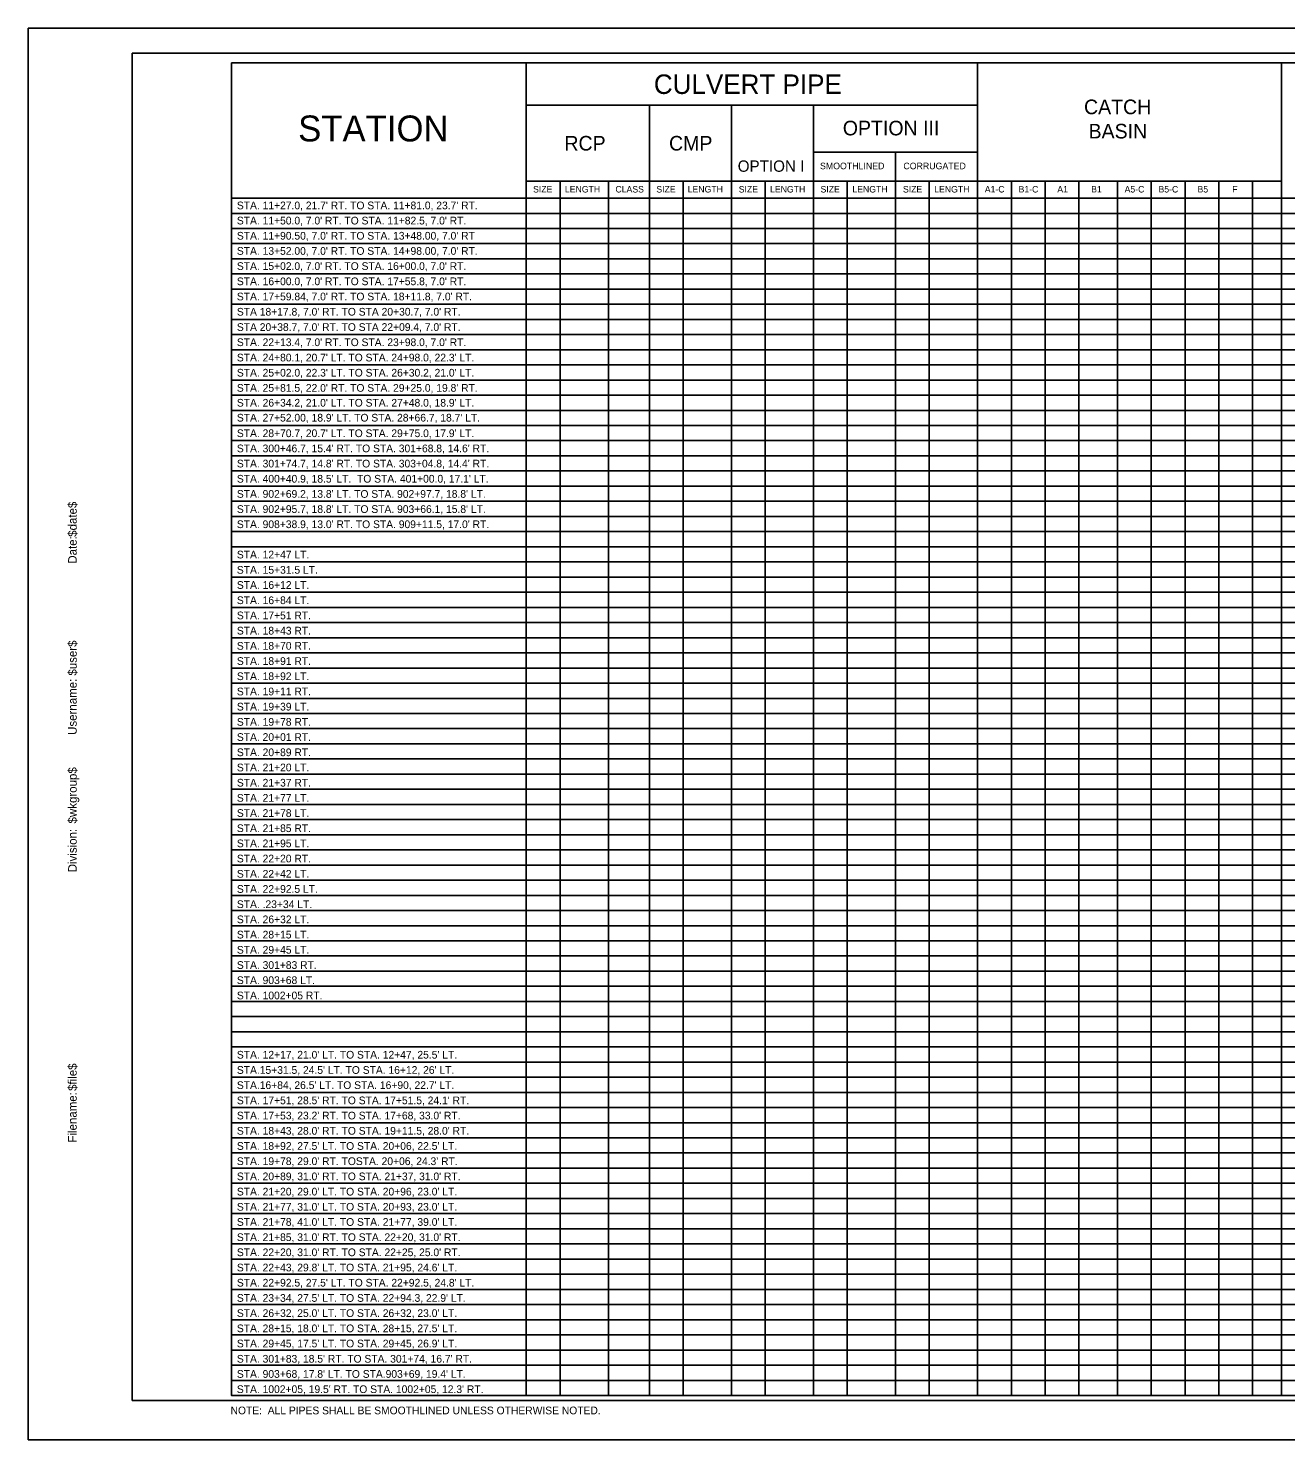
# Model space of a CAD drawing. Extents: x -0.13 to 2.7, y -0.05 to 1.78.
# Drawn here: x -0.135 to 1.498, y -0.051 to 1.782 of the extents above; entities that cross this region are included whole.
import ezdxf

# ---------------------------------------------------------------- set-up
doc = ezdxf.new("R2010")
doc.units = 0
for name, color, linetype in [('ANNOTATION', 7, 'Continuous'), ('BORDER', 7, 'Continuous'), ('PLOT BOUNDARY', 7, 'Continuous')]:
    doc.layers.add(name, color=color, linetype=linetype)

msp = doc.modelspace()

# ---------------------------------------------------------------- linework, layer by layer
at = {"layer": 'BORDER'}
for p, q in [((2.6667, 1.75), (0, 1.75)), ((0, 1.75), (0, 0)), ((0.512, 1.6825), (0.512, 1.7373)), ((1.0982, 1.6825), (1.0982, 1.7373)), ((1.4929, 0.0065), (1.4929, 1.7373)), ((0.512, 1.6214), (0.512, 1.6825)), ((0.512, 1.6825), (0.5559, 1.6825)), ((0.5559, 1.6825), (0.6186, 1.6825)), ((0.6186, 1.6825), (0.6719, 1.6825)), ((0.6719, 1.6214), (0.6719, 1.6825)), ((0.6719, 1.6825), (0.7158, 1.6825)), ((0.7158, 1.6825), (0.7785, 1.6825)), ((0.7785, 1.6214), (0.7785, 1.6825)), ((0.7785, 1.6825), (0.8223, 1.6825)), ((0.8223, 1.6825), (0.9289, 1.6825)), ((0.885, 1.5836), (0.885, 1.6825)), ((0.9289, 1.6825), (1.0982, 1.6825)), ((1.0982, 1.6214), (1.0982, 1.6825)), ((0.512, 1.5836), (0.512, 1.6214)), ((0.6719, 1.5836), (0.6719, 1.6214)), ((0.7785, 1.5836), (0.7785, 1.6214)), ((0.885, 1.6214), (0.9289, 1.6214)), ((0.9289, 1.6214), (1.0354, 1.6214)), ((0.9916, 1.5616), (0.9916, 1.6214)), ((1.0354, 1.6214), (1.0982, 1.6214)), ((1.0982, 1.5836), (1.0982, 1.6214)), ((0.512, 1.5616), (0.512, 1.5836)), ((0.512, 1.5836), (0.5559, 1.5836)), ((0.5559, 1.5616), (0.5559, 1.5836)), ((0.5559, 1.5836), (0.6186, 1.5836)), ((0.6186, 1.5616), (0.6186, 1.5836)), ((0.6186, 1.5836), (0.6719, 1.5836)), ((0.6719, 1.5616), (0.6719, 1.5836)), ((0.6719, 1.5836), (0.7158, 1.5836)), ((0.7158, 1.5616), (0.7158, 1.5836)), ((0.7158, 1.5836), (0.7785, 1.5836)), ((0.7785, 1.5616), (0.7785, 1.5836)), ((0.7785, 1.5836), (0.8223, 1.5836)), ((0.8223, 1.5616), (0.8223, 1.5836)), ((0.8223, 1.5836), (0.885, 1.5836)), ((0.885, 1.5616), (0.885, 1.5836)), ((0.885, 1.5836), (0.9289, 1.5836)), ((0.9289, 1.5616), (0.9289, 1.5836)), ((0.9289, 1.5836), (0.9916, 1.5836)), ((0.9916, 1.5836), (1.0354, 1.5836)), ((1.0354, 1.5616), (1.0354, 1.5836)), ((1.0354, 1.5836), (1.0982, 1.5836)), ((1.0982, 1.5616), (1.0982, 1.5836)), ((1.0982, 1.5836), (1.142, 1.5836)), ((1.142, 1.5616), (1.142, 1.5836)), ((1.142, 1.5836), (1.1858, 1.5836)), ((1.1858, 1.5616), (1.1858, 1.5836)), ((1.1858, 1.5836), (1.2298, 1.5836)), ((1.2298, 1.5616), (1.2298, 1.5836)), ((1.2298, 1.5836), (1.2548, 1.5836)), ((1.2548, 1.5836), (1.2798, 1.5836)), ((1.2798, 1.5616), (1.2798, 1.5836)), ((1.2798, 1.5836), (1.3237, 1.5836)), ((1.3237, 1.5616), (1.3237, 1.5836)), ((1.3237, 1.5836), (1.3676, 1.5836)), ((1.3676, 1.5616), (1.3676, 1.5836)), ((1.3676, 1.5836), (1.4929, 1.5836)), ((1.4115, 1.5616), (1.4115, 1.5836)), ((1.4554, 1.5616), (1.4554, 1.5836)), ((0.512, 1.5616), (0.512, 0.0065)), ((0.5559, 1.5616), (0.5559, 0.0065)), ((0.6186, 1.5616), (0.6186, 0.0065)), ((0.6719, 1.5616), (0.6719, 0.0065)), ((0.7158, 1.5616), (0.7158, 0.0065)), ((0.7785, 1.5616), (0.7785, 0.0065)), ((0.8223, 1.5616), (0.8223, 0.0065)), ((0.885, 1.5616), (0.885, 0.0065)), ((0.9289, 1.5616), (0.9289, 0.0065)), ((0.9916, 1.5616), (0.9916, 0.0065)), ((1.0354, 1.5616), (1.0354, 0.0065)), ((1.0982, 1.5616), (1.0982, 0.0065)), ((1.142, 1.5616), (1.142, 0.0065)), ((1.1858, 1.5616), (1.1858, 0.0065)), ((1.2298, 1.5616), (1.2298, 0.0065)), ((1.2798, 1.5616), (1.2798, 0.0065)), ((1.3237, 1.5616), (1.3237, 0.0065)), ((1.3676, 1.5616), (1.3676, 0.0065)), ((1.4115, 1.5616), (1.4115, 0.0065)), ((1.4554, 1.5616), (1.4554, 0.0065)), ((0.1293, 1.5419), (2.3707, 1.5419)), ((0.1293, 1.5223), (2.3707, 1.5223)), ((0.1293, 1.5026), (2.3707, 1.5026)), ((0.1293, 1.4829), (2.3707, 1.4829)), ((0.1293, 1.4632), (2.3707, 1.4632)), ((0.1293, 1.4435), (2.3707, 1.4435)), ((0.1293, 1.4238), (2.3707, 1.4238)), ((0.1293, 1.4041), (2.3707, 1.4041)), ((0.1293, 1.3845), (2.3707, 1.3845)), ((0.1293, 1.3648), (2.3707, 1.3648)), ((0.1293, 1.3451), (2.3707, 1.3451)), ((0.1293, 1.3254), (2.3707, 1.3254)), ((0.1293, 1.3057), (2.3707, 1.3057)), ((0.1293, 1.286), (2.3707, 1.286)), ((0.1293, 1.2664), (2.3707, 1.2664)), ((0.1293, 1.2467), (2.3707, 1.2467)), ((0.1293, 1.227), (2.3707, 1.227)), ((0.1293, 1.2073), (2.3707, 1.2073)), ((0.1293, 1.1876), (2.3707, 1.1876)), ((0.1293, 1.1679), (2.3707, 1.1679)), ((0.1293, 1.1482), (2.3707, 1.1482)), ((0.1293, 1.1286), (2.3707, 1.1286)), ((0.1293, 1.1089), (2.3707, 1.1089)), ((0.1293, 1.0892), (2.3707, 1.0892)), ((0.1293, 1.0695), (2.3707, 1.0695)), ((0.1293, 1.0498), (2.3707, 1.0498)), ((0.1293, 1.0301), (2.3707, 1.0301)), ((0.1293, 1.0104), (2.3707, 1.0104)), ((0.1293, 0.9908), (2.3707, 0.9908)), ((0.1293, 0.9711), (2.3707, 0.9711)), ((0.1293, 0.9514), (2.3707, 0.9514)), ((0.1293, 0.9317), (2.3707, 0.9317)), ((0.1293, 0.912), (2.3707, 0.912)), ((0.1293, 0.8923), (2.3707, 0.8923)), ((0.1293, 0.8727), (2.3707, 0.8727)), ((0.1293, 0.853), (2.3707, 0.853)), ((0.1293, 0.8333), (2.3707, 0.8333)), ((0.1293, 0.8136), (2.3707, 0.8136)), ((0.1293, 0.7939), (2.3707, 0.7939)), ((0.1293, 0.7742), (2.3707, 0.7742)), ((0.1293, 0.7545), (2.3707, 0.7545)), ((0.1293, 0.7349), (2.3707, 0.7349)), ((0.1293, 0.7152), (2.3707, 0.7152)), ((0.1293, 0.6955), (2.3707, 0.6955)), ((0.1293, 0.6758), (2.3707, 0.6758)), ((0.1293, 0.6561), (2.3707, 0.6561)), ((0.1293, 0.6364), (2.3707, 0.6364)), ((0.1293, 0.6167), (2.3707, 0.6167)), ((0.1293, 0.5971), (2.3707, 0.5971)), ((0.1293, 0.5774), (2.3707, 0.5774)), ((0.1293, 0.5577), (2.3707, 0.5577)), ((0.1293, 0.538), (2.3707, 0.538)), ((0.1293, 0.5183), (2.3707, 0.5183)), ((0.1293, 0.4986), (2.3707, 0.4986)), ((0.1293, 0.479), (2.3707, 0.479)), ((0.1293, 0.4593), (2.3707, 0.4593)), ((0.1293, 0.4396), (2.3707, 0.4396)), ((0.1293, 0.4199), (2.3707, 0.4199)), ((0.1293, 0.4002), (2.3707, 0.4002)), ((0.1293, 0.3805), (2.3707, 0.3805)), ((0.1293, 0.3608), (2.3707, 0.3608)), ((0.1293, 0.3412), (2.3707, 0.3412)), ((0.1293, 0.3215), (2.3707, 0.3215)), ((0.1293, 0.3018), (2.3707, 0.3018)), ((0.1293, 0.2821), (2.3707, 0.2821)), ((0.1293, 0.2624), (2.3707, 0.2624)), ((0.1293, 0.2427), (2.3707, 0.2427)), ((0.1293, 0.223), (2.3707, 0.223)), ((0.1293, 0.2034), (2.3707, 0.2034)), ((0.1293, 0.1837), (2.3707, 0.1837)), ((0.1293, 0.164), (2.3707, 0.164)), ((0.1293, 0.1443), (2.3707, 0.1443)), ((0.1293, 0.1246), (2.3707, 0.1246)), ((0.1293, 0.1049), (2.3707, 0.1049)), ((0.1293, 0.0853), (2.3707, 0.0853)), ((0.1293, 0.0656), (2.3707, 0.0656)), ((0.1293, 0.0459), (2.3707, 0.0459)), ((0.1293, 0.0262), (2.3707, 0.0262)), ((0, 0), (2.6667, 0)), ((0.1293, 0.0065), (2.3707, 0.0065))]:
    msp.add_line(p, q, dxfattribs=at)
msp.add_lwpolyline([(0.1293, 1.7373), (2.3707, 1.7373), (2.3707, 1.5616), (0.1293, 1.5616)], close=True, dxfattribs=at)
msp.add_lwpolyline([(0.1293, 1.5616), (0.1293, 0.0065), (2.3707, 0.0065), (2.3707, 1.5616)], dxfattribs=at)
at = {"layer": 'PLOT BOUNDARY'}
msp.add_lwpolyline([(-0.1349, -0.051), (2.6984, -0.051), (2.6984, 1.7823), (-0.1349, 1.7823)], close=True, dxfattribs=at)

# ---------------------------------------------------------------- texts
at = {"layer": 'ANNOTATION'}
for s, p in [("STA. 11+27.0, 21.7' RT. TO STA. 11+81.0, 23.7' RT.", (0.1361, 1.5472)), ("STA. 11+50.0, 7.0' RT. TO STA. 11+82.5, 7.0' RT.", (0.1361, 1.5275)), ("STA. 11+90.50, 7.0' RT. TO STA. 13+48.00, 7.0' RT", (0.1361, 1.5078)), ("STA. 13+52.00, 7.0' RT. TO STA. 14+98.00, 7.0' RT.", (0.1361, 1.4881)), ("STA. 15+02.0, 7.0' RT. TO STA. 16+00.0, 7.0' RT.", (0.1361, 1.4684)), ("STA. 16+00.0, 7.0' RT. TO STA. 17+55.8, 7.0' RT. ", (0.1361, 1.4486)), ("STA. 17+59.84, 7.0' RT. TO STA. 18+11.8, 7.0' RT.", (0.1361, 1.4289)), ("STA 18+17.8, 7.0' RT. TO STA 20+30.7, 7.0' RT.", (0.1361, 1.4091)), ("STA 20+38.7, 7.0' RT. TO STA 22+09.4, 7.0' RT.", (0.1361, 1.3892)), ("STA. 22+13.4, 7.0' RT. TO STA. 23+98.0, 7.0' RT.", (0.1361, 1.3695)), ("STA. 24+80.1, 20.7' LT. TO STA. 24+98.0, 22.3' LT.", (0.1361, 1.3496)), ("STA. 25+02.0, 22.3' LT. TO STA. 26+30.2, 21.0' LT.", (0.1361, 1.3299)), ("STA. 25+81.5, 22.0' RT. TO STA. 29+25.0, 19.8' RT.", (0.1361, 1.3102)), ("STA. 26+34.2, 21.0' LT. TO STA. 27+48.0, 18.9' LT.", (0.1361, 1.2909)), ("STA. 27+52.00, 18.9' LT. TO STA. 28+66.7, 18.7' LT.", (0.1361, 1.2715)), ("STA. 28+70.7, 20.7' LT. TO STA. 29+75.0, 17.9' LT.", (0.1361, 1.2513)), ("STA. 300+46.7, 15.4' RT. TO STA. 301+68.8, 14.6' RT.", (0.1361, 1.2316)), ("STA. 301+74.7, 14.8' RT. TO STA. 303+04.8, 14.4' RT.", (0.1361, 1.2119)), ("STA. 400+40.9, 18.5' LT.  TO STA. 401+00.0, 17.1' LT.", (0.1361, 1.1922)), ("STA. 902+69.2, 13.8' LT. TO STA. 902+97.7, 18.8' LT.", (0.1361, 1.1725)), ("STA. 902+95.7, 18.8' LT. TO STA. 903+66.1, 15.8' LT.", (0.1361, 1.1528)), ("STA. 908+38.9, 13.0' RT. TO STA. 909+11.5, 17.0' RT.", (0.1361, 1.1331)), ('STA. 12+47 LT.', (0.1361, 1.0937)), ('STA. 15+31.5 LT.', (0.1361, 1.0739)), ('STA. 16+12 LT.', (0.1361, 1.0542)), ('STA. 16+84 LT.', (0.1361, 1.0344)), ('STA. 17+51 RT.', (0.1361, 1.0147)), ('STA. 18+43 RT.', (0.1361, 0.9949)), ('STA. 18+70 RT.', (0.1361, 0.9752)), ('STA. 18+91 RT.', (0.1361, 0.9554)), ('STA. 18+92 LT.', (0.1361, 0.9357)), ('STA. 19+11 RT.', (0.1361, 0.9159)), ('STA. 19+39 LT.', (0.1361, 0.8962)), ('STA. 19+78 RT.', (0.1361, 0.8764)), ('STA. 20+01 RT.', (0.1361, 0.8567)), ('STA. 20+89 RT.', (0.1361, 0.8369)), ('STA. 21+20 LT.', (0.1361, 0.8172)), ('STA. 21+37 RT.', (0.1361, 0.7974)), ('STA. 21+77 LT.', (0.1361, 0.7777)), ('STA. 21+78 LT.', (0.1361, 0.758)), ('STA. 21+85 RT.', (0.1361, 0.7383)), ('STA. 21+95 LT.', (0.1361, 0.7186)), ('STA. 22+20 RT.', (0.1361, 0.6989)), ('STA. 22+42 LT.', (0.1361, 0.6791)), ('STA. 22+92.5 LT.', (0.1361, 0.6594)), ('STA. .23+34 LT.', (0.1361, 0.6396)), ('STA. 26+32 LT.', (0.1361, 0.6199)), ('STA. 28+15 LT.', (0.1361, 0.6001)), ('STA. 29+45 LT.', (0.1361, 0.5804)), ('STA. 301+83 RT.', (0.1361, 0.5606)), ('STA. 903+68 LT.', (0.1361, 0.5409)), ('STA. 1002+05 RT.', (0.1361, 0.5211)), ("STA. 12+17, 21.0' LT. TO STA. 12+47, 25.5' LT.", (0.1361, 0.4441)), ("STA.15+31.5, 24.5' LT. TO STA. 16+12, 26' LT.", (0.1361, 0.4243)), ("STA.16+84, 26.5' LT. TO STA. 16+90, 22.7' LT.", (0.1361, 0.4046)), ("STA. 17+51, 28.5' RT. TO STA. 17+51.5, 24.1' RT.", (0.1361, 0.3848)), ("STA. 17+53, 23.2' RT. TO STA. 17+68, 33.0' RT.", (0.1361, 0.3651)), ("STA. 18+43, 28.0' RT. TO STA. 19+11.5, 28.0' RT.", (0.1361, 0.3453)), ("STA. 18+92, 27.5' LT. TO STA. 20+06, 22.5' LT.", (0.1361, 0.3256)), ("STA. 19+78, 29.0' RT. TOSTA. 20+06, 24.3' RT.", (0.1361, 0.3058)), ("STA. 20+89, 31.0' RT. TO STA. 21+37, 31.0' RT.", (0.1361, 0.2861)), ("STA. 21+20, 29.0' LT. TO STA. 20+96, 23.0' LT.", (0.1361, 0.2663)), ("STA. 21+77, 31.0' LT. TO STA. 20+93, 23.0' LT.", (0.1361, 0.2466)), ("STA. 21+78, 41.0' LT. TO STA. 21+77, 39.0' LT.", (0.1361, 0.2269)), ("STA. 21+85, 31.0' RT. TO STA. 22+20, 31.0' RT.", (0.1361, 0.2071)), ("STA. 22+20, 31.0' RT. TO STA. 22+25, 25.0' RT.", (0.1361, 0.1875)), ("STA. 22+43, 29.8' LT. TO STA. 21+95, 24.6' LT.", (0.1361, 0.1677)), ("STA. 22+92.5, 27.5' LT. TO STA. 22+92.5, 24.8' LT.", (0.1361, 0.148)), ("STA. 23+34, 27.5' LT. TO STA. 22+94.3, 22.9' LT.", (0.1361, 0.1282)), ("STA. 26+32, 25.0' LT. TO STA. 26+32, 23.0' LT.", (0.1361, 0.1085)), ("STA. 28+15, 18.0' LT. TO STA. 28+15, 27.5' LT.", (0.1361, 0.0887)), ("STA. 29+45, 17.5' LT. TO STA. 29+45, 26.9' LT.", (0.1361, 0.069)), ("STA. 301+83, 18.5' RT. TO STA. 301+74, 16.7' RT.", (0.1361, 0.0492)), ("STA. 903+68, 17.8' LT. TO STA.903+69, 19.4' LT.", (0.1361, 0.0295)), ("STA. 1002+05, 19.5' RT. TO STA. 1002+05, 12.3' RT.", (0.1361, 0.0097)), ('NOTE:  ALL PIPES SHALL BE SMOOTHLINED UNLESS OTHERWISE NOTED.', (0.1279, -0.0179))]:
    msp.add_text(s, height=0.01, dxfattribs=at).set_placement(p)
at = {"layer": 'BORDER'}
for s, height, p in [('CULVERT PIPE', 0.025276, (0.6777, 1.697)), ('CATCH', 0.01896, (1.2364, 1.6707)), ('STATION', 0.0337, (0.2157, 1.6353)), ('OPTION III', 0.01896, (0.9231, 1.6432)), ('BASIN', 0.01896, (1.2423, 1.6392)), ('RCP', 0.01896, (0.5615, 1.6235)), ('CMP', 0.01896, (0.6974, 1.6235)), ('OPTION I', 0.01474, (0.7866, 1.5959)), ('SMOOTHLINED', 0.008531, (0.8935, 1.5992)), ('CORRUGATED', 0.00853, (1.0018, 1.5992)), ('SIZE', 0.00843, (0.5208, 1.569)), ('LENGTH', 0.00843, (0.5622, 1.569)), ('CLASS', 0.00843, (0.6278, 1.569)), ('SIZE', 0.00843, (0.6809, 1.569)), ('LENGTH', 0.00843, (0.7216, 1.569)), ('SIZE', 0.00843, (0.7879, 1.569)), ('LENGTH', 0.00843, (0.8286, 1.569)), ('SIZE', 0.00843, (0.8942, 1.569)), ('LENGTH', 0.00843, (0.9355, 1.569)), ('SIZE', 0.00843, (1.0012, 1.569)), ('LENGTH', 0.00843, (1.0418, 1.569)), ('A1-C', 0.00843, (1.1075, 1.569)), ('B1-C', 0.00843, (1.1514, 1.569)), ('A1', 0.00843, (1.2017, 1.569)), ('B1', 0.00843, (1.2457, 1.569)), ('A5-C', 0.00843, (1.2891, 1.569)), ('B5-C', 0.00843, (1.3331, 1.569)), ('B5', 0.00843, (1.3838, 1.569)), ('F', 0.00843, (1.4289, 1.569))]:
    msp.add_text(s, height=height, dxfattribs=at).set_placement(p)
for s, p in [('$date$', (-0.0719, 1.1218)), ('Date:', (-0.0719, 1.0869)), ('$user$', (-0.0719, 0.9415)), ('Username:', (-0.0719, 0.8645)), ('$wkgroup$', (-0.0719, 0.7495)), ('Division:', (-0.0719, 0.6861)), ('$file$', (-0.0719, 0.4021)), ('Filename:', (-0.0719, 0.335))]:
    msp.add_text(s, height=0.01116, rotation=90, dxfattribs=at).set_placement(p)

doc.saveas('drawing.dxf')
